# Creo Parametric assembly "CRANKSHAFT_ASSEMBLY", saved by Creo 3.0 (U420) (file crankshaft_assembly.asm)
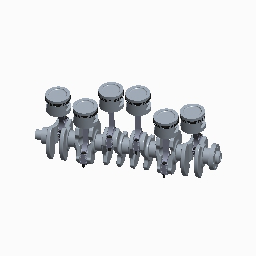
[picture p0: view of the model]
Units: millimeter Kilogram Sec (mmKs); MM, KILOGRAM, SECS

Created from: INLBS_ASM_DESIGN.ASM

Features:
  1. datum plane "ASM_RIGHT"
  2. datum plane "ASM_TOP"
  3. datum plane "ASM_FRONT"
  4. coordinate system
  5. pattern "Pattern 1"
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
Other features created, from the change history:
  datum plane "ADTM1"
  datum plane "ADTM2"
  datum plane "ADTM3"
  datum plane "ADTM4"
  datum plane "ADTM5"
  datum plane "ADTM6"
  datum axis "AA_1" (2 times)
  pattern "Pattern 2"
  datum axis "AA_2"
  datum axis "AA_3"
  datum axis "AA_4"
  datum axis "AA_5"
  datum axis "AA_6"
  component "CRANKSHAFT.PRT" (2 times)
  component "CRANKSHAFT"
  component "PISTON_ASSEMBLY" (6 times)
  pattern "Pattern 3"
  component "PISTON_ASSEMBLY.ASM" (5 times)
  component "CONNECTING_ROD_ASSEMBLY.ASM"
  component "CONNECTING_ROD_ASSEMBLY" (6 times)
  planar section "A" (2 times)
